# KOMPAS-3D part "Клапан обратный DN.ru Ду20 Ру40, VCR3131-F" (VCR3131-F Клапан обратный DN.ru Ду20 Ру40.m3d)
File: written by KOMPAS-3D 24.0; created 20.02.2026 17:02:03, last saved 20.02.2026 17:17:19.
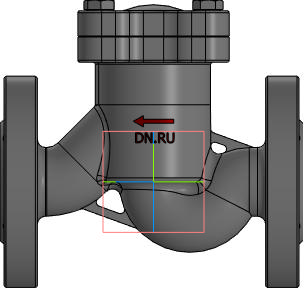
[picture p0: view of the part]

Document properties: Автор: R2D2; Полное имя файла: VCR3131-F Клапан обратный DN.ru Ду20 Ру40.cdw

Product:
- Body: Тело 3  | qty 1
    Масса: 4.829539
- Part/product: Клапан обратный DN.ru Ду20 Ру40  | designation VCR3131-F
    Масса: 3.8
    Раздел спецификации: Прочие изделия
    Форматы листов документа: A3
    Примечание: D100-04037
    additional columns: D100-04037

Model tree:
1. Операция без истории:1

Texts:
  VCR3131-F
